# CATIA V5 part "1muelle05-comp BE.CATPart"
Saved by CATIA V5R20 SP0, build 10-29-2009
Part number: 1muelle05-comp BE
Revision: ANY
Definition: UNKNOWN
Nomenclature: 1muelle05-comp BE
Source: Unknown
Bounding box of the stored display mesh (mm): x -4.4 to 4.4, y -4.4 to 4.4, z -0.001 to 8.249
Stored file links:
  C:\Users\Utente\Desktop\IO LAVORO\3D X SITO CF\CUMSA\3D files BE\BE 051317\1muelle05-comp BE.CATPart
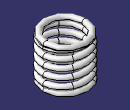
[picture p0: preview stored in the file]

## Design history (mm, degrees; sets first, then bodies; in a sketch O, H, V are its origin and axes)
Set1 "FacciaKO#NONE#5269"
  DatumSurface1 "Sup5269_1"
  DatumCurve1 "Crv5269_1"
Set2 "FacciaKO#NONE#5271"
  DatumSurface2 "Sup5271_1"
  DatumCurve2 "Crv5271_1"
Body1 "Cortar-Extruir1" (main body)
  Solid1: solid without history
